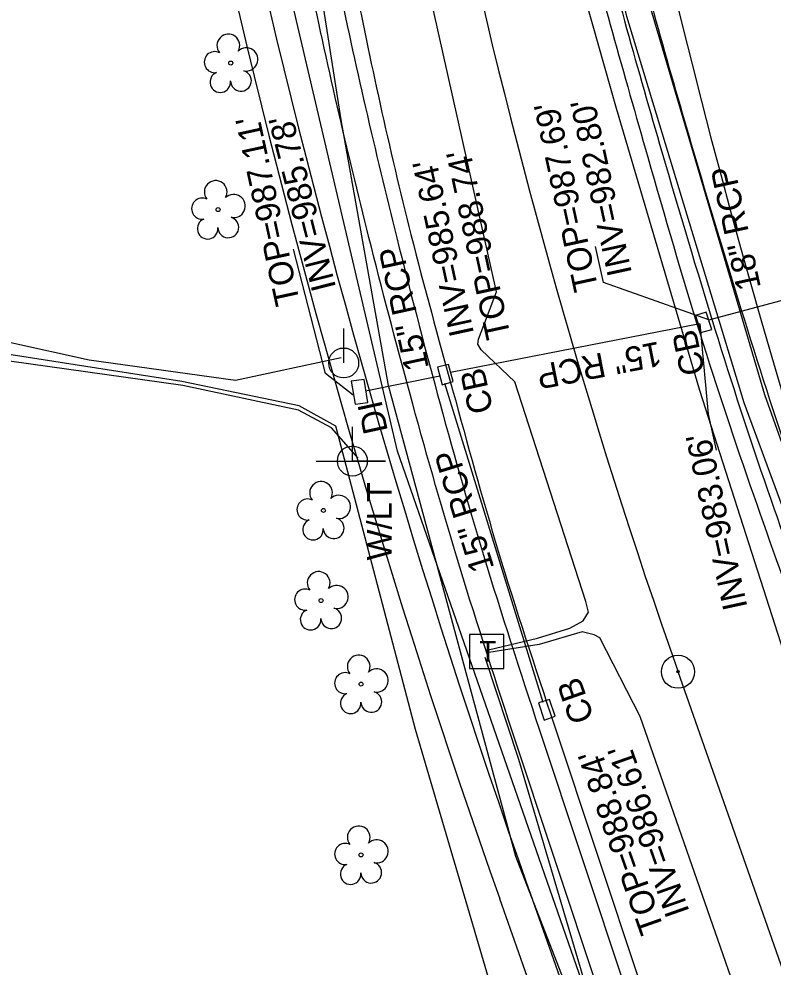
# Model space of a CAD drawing. Extents: x 1614611 to 1617571, y 898867 to 905462.
# Drawn here: x 1615972.1 to 1616095.5, y 904280.1 to 904435.2 of the extents above; entities that cross this region are included whole.
import ezdxf

# ---------------------------------------------------------------- set-up
doc = ezdxf.new("R2010")
doc.units = 0
for name, color, linetype in [('Exist Boundary Watershed Residential C 05', 7, 'Continuous'), ('Exist Horizontal Alignment Tick Label', 7, 'Continuous'), ('Exist Structure Minor Catch Basin Top Elevation', 7, 'Continuous'), ('Exist Structure Minor Drop Inlet Top Elevation', 7, 'Continuous'), ('Exist Structure Minor Pipes RCP 15 Inch Invert', 7, 'Continuous'), ('Exist Structure Minor Pipes RCP 18 Inch Invert', 7, 'Continuous'), ('Exist Survey Centerline Point CELL', 7, 'Continuous'), ('Exist Utilities Gas UG Line SUE LOS B', 7, 'Continuous'), ('Exist Utilities Power Joint Use Telephone CELL', 7, 'Continuous'), ('Exist Utilities Power Joint Use Telephone Text', 7, 'Continuous'), ('Exist Utilities Power Pole CELL', 7, 'Continuous'), ('Exist Utilities Telephone Pedestal CELL', 7, 'Continuous'), ('Exist Utilities Telephone UG Cable SUE LOS B', 7, 'Continuous'), ('Exist Utilities Telephone UG FO SUE LOS B', 7, 'Continuous'), ('Exist Utilities Telephone UG FO SUE LOS C', 7, 'Continuous'), ('Exist Utilities TV UG Cable SUE LOS B', 7, 'Continuous'), ('Exist Utilities TV UG FO Cable SUE LOS B', 7, 'Continuous'), ('Exist Utilities Water UG Line SUE LOS B', 7, 'Continuous'), ('Exist Vegetation Tree CELL', 7, 'Continuous'), ('Prop Drainage Structure Catch Basin Adjust CELL', 7, 'Continuous'), ('Prop Drainage Structure Catch Basin Grate 840 03E Label', 7, 'Continuous'), ('Prop Drainage Structure Catch Basin Open Throat 4 CELL', 7, 'Continuous'), ('Prop Drainage Structure Drop Inlet Grate 3 Narrow Slots and Sag Grates 840 24 Label', 7, 'Continuous'), ('Prop Drainage Structure Removal Label', 7, 'Continuous'), ('Prop Earthen Structure Cut Ditch Special Back of Curb Detail CELL', 7, 'Continuous'), ('Prop Earthen Structure Head Ditch Label', 7, 'Continuous'), ('Prop Easement Permanent Drainage', 7, 'Continuous'), ('Prop Erosion Embankment Toe Protection CELL', 7, 'Continuous'), ('Prop Erosion Embankment Toe Protection with Rip Rap 2 Detail CELL', 7, 'Continuous'), ('Prop Erosion Embankment Toe Protection with Rip Rap 3 Detail CELL', 7, 'Continuous'), ('Prop Plan Preparation Drainage Notes Label', 7, 'Continuous'), ('Prop Plan Preparation Table Ditch Data CELL', 7, 'Continuous'), ('Raster_Level_2', 7, 'Continuous'), ('Scratch_Level_1', 7, 'Continuous'), ('Scratch_Level_9', 7, 'Continuous')]:
    doc.layers.add(name, color=color, linetype=linetype)

# ---------------------------------------------------------------- blocks, each defined once
blk = doc.blocks.new('EXIST SURVEY CENTERLINE POINT')
at = {"layer": 'Exist Survey Centerline Point CELL'}
for radius in [0.0542, 0.00375]:
    blk.add_circle((0, 0), radius, dxfattribs=at)
blk = doc.blocks.new('EXIST UTILITIES TELEPHONE PEDESTAL')
at = {"layer": 'Exist Utilities Telephone Pedestal CELL'}
blk.add_line((0, 0), (0, 0), dxfattribs=at)
blk.add_lwpolyline([(-0.0545, -0.0565), (0.0574, -0.0565), (0.0574, 0.0554), (-0.0545, 0.0554), (-0.0545, -0.0565)], dxfattribs=at)
blk.add_text('T', height=0.0684, dxfattribs=at).set_placement((-0.0226, -0.0343))

msp = doc.modelspace()

# ---------------------------------------------------------------- linework, layer by layer
at = {"layer": 'Exist Boundary Watershed Residential C 05'}
msp.add_line((1616057.2, 904319.01), (1616071.33, 904276.54), dxfattribs=at)
for points in [[(1616036.89, 904712.38), (1616036.47, 904709.78), (1616036.41, 904704.57), (1616037.92, 904663.56), (1616040.29, 904622.52), (1616044.13, 904581.91), (1616049.52, 904539.43), (1616056.84, 904495.96), (1616066.12, 904453.97), (1616077.29, 904413.44), (1616085.97, 904384.46), (1616094.57, 904358.18), (1616103.14, 904334.3)], [(1615997.37, 904708.66), (1615998.49, 904661.09), (1616001.16, 904617.42), (1616004.97, 904575.65), (1616009.84, 904531.84), (1616016.05, 904486.99), (1616024.12, 904442.16), (1616033.92, 904399.38), (1616040.54, 904373.92), (1616048.1, 904347.47), (1616057.2, 904319.01)]]:
    msp.add_spline(points, degree=3, dxfattribs=at)
at = {"layer": 'Exist Utilities Gas UG Line SUE LOS B'}
msp.add_lwpolyline([(1616112.81, 904150.47), (1616095.02, 904196.89), (1616086.93, 904216.94), (1616080.62, 904232.37), (1616061.55, 904277.17), (1616053.37, 904298.2), (1616032.55, 904375.26), (1616024.82, 904418.68), (1616016.83, 904469.58), (1616008.07, 904526.35), (1616004.5, 904556.45)], dxfattribs=at)
at = {"layer": 'Exist Utilities Power Joint Use Telephone CELL'}
msp.add_line((1616026.64, 904362.88), (1616026.64, 904362.88), dxfattribs=at)
msp.add_lwpolyline([(1616020.71, 904362.88), (1616032.04, 904362.85), (1616026.64, 904362.86), (1616026.64, 904368.51)], dxfattribs=at)
msp.add_circle((1616026.64, 904362.89), 2.45, dxfattribs=at)
at = {"layer": 'Exist Utilities Power Pole CELL'}
for q in [(1616025.22, 904384.55), (1616025.22, 904378.93)]:
    msp.add_line((1616025.22, 904378.93), q, dxfattribs=at)
msp.add_circle((1616025.22, 904378.93), 2.45, dxfattribs=at)
at = {"layer": 'Exist Utilities Telephone UG Cable SUE LOS B'}
for points in [[(1616048.94, 904332.04), (1616056.91, 904333.91), (1616062.21, 904335.58), (1616064.42, 904336.78), (1616065.29, 904338.19), (1616064.86, 904339.94), (1616053.21, 904375.85), (1616047.74, 904381.07), (1616047.16, 904382.03), (1616047.3, 904382.84), (1616050.2, 904390.58), (1616036.77, 904450.77), (1616023.33, 904513.19), (1616016.15, 904558.39)], [(1616264.73, 903785.56), (1616225.23, 903895.34), (1616215.6, 903922.1), (1616202.44, 903959.77), (1616193.59, 903987.06), (1616171.78, 904048.65), (1616147.44, 904117.95), (1616126.43, 904148.49), (1616103.05, 904238.24), (1616092.8, 904266.31), (1616073.76, 904321.1), (1616067.14, 904333.96), (1616066.19, 904334.49), (1616064.27, 904334.96), (1616057.18, 904332.89), (1616048.96, 904331.57)], [(1616048.33, 904330.8), (1616053.85, 904314.12), (1616064.53, 904278.06), (1616076.61, 904243.93), (1616083.17, 904220.39), (1616080.21, 904212.01), (1616079.68, 904210.16), (1616080.3, 904208.81)]]:
    msp.add_lwpolyline(points, dxfattribs=at)
at = {"layer": 'Exist Utilities Telephone UG FO SUE LOS B'}
for points in [[(1616227.47, 903998.34), (1616211.12, 904046.11), (1616197.17, 904083.61), (1616180.84, 904129.23), (1616169.23, 904161.39), (1616162.49, 904178.57), (1616139.6, 904240.02), (1616090.77, 904372.44), (1616071.57, 904435.61), (1616056.71, 904499.76), (1616046.9, 904559.71)], [(1616172.98, 904168.79), (1616171.02, 904169.17), (1616169.94, 904170.68), (1616165.82, 904179.93), (1616142.94, 904241.46), (1616115.62, 904313.42), (1616094.14, 904373.71), (1616075.4, 904437.07), (1616059.87, 904500.59), (1616050.65, 904559.97)]]:
    msp.add_lwpolyline(points, dxfattribs=at)
at = {"layer": 'Exist Utilities Telephone UG FO SUE LOS C'}
msp.add_line((1616110.16, 904145.65), (1616034.02, 904364.51), dxfattribs=at)
msp.add_lwpolyline([(1616034.02, 904364.51), (1616014.41, 904448.18), (1615992.34, 904593.02)], dxfattribs=at)
at = {"layer": 'Exist Utilities TV UG Cable SUE LOS B'}
msp.add_lwpolyline([(1616027.58, 904363.35), (1616023.21, 904368.31), (1616017.83, 904371.19), (1615998.91, 904375.25), (1615970.55, 904379.25), (1615936.7, 904383.75), (1615897.49, 904393.93), (1615866.72, 904404.04), (1615862.97, 904406.89), (1615854.55, 904417.3), (1615840.06, 904422.53), (1615819.41, 904426.03), (1615794.82, 904424.38), (1615770.62, 904419.24), (1615748.65, 904413.39), (1615748.63, 904413.39)], dxfattribs=at)
at = {"layer": 'Exist Utilities TV UG FO Cable SUE LOS B'}
msp.add_lwpolyline([(1616082.03, 904205.63), (1616078.76, 904211.5), (1616072.95, 904217.64), (1616063.83, 904236.79), (1616050.03, 904274.65), (1616036.99, 904318.99), (1616023.92, 904368.58), (1616017.91, 904371.93), (1615998.76, 904375.92), (1615970.79, 904380.24), (1615936.88, 904384.46), (1615897.53, 904394.73), (1615867.22, 904404.56), (1615863.54, 904407.73), (1615855.35, 904417.46), (1615839.69, 904423.44), (1615819.45, 904426.72), (1615794.88, 904425.22), (1615770.33, 904420), (1615748.51, 904414.05)], dxfattribs=at)
at = {"layer": 'Exist Utilities Water UG Line SUE LOS B'}
msp.add_lwpolyline([(1616526.94, 903118.95), (1616504.59, 903181.23), (1616480.02, 903252.46), (1616446.17, 903345), (1616411.28, 903445.17), (1616385.62, 903515.15), (1616350.02, 903616.87), (1616323.73, 903691.37), (1616291.21, 903786.26), (1616260.45, 903872.07), (1616224.66, 903974.02), (1616192.08, 904066.13), (1616173.94, 904118.11), (1616130.42, 904237.78), (1616097.26, 904331.65), (1616083.48, 904374.45), (1616069.85, 904420.53), (1616059.14, 904458.49), (1616050.85, 904496.39), (1616045.84, 904527.76), (1616030.28, 904669.9)], dxfattribs=at)
at = {"layer": 'Exist Vegetation Tree CELL'}
for p, q in [((1616006.73, 904427.99), (1616006.73, 904427.99)), ((1616004.67, 904404.02), (1616004.67, 904404.02)), ((1616021.91, 904354.81), (1616021.91, 904354.81)), ((1616021.51, 904340.08), (1616021.51, 904340.08)), ((1616028.07, 904326.4), (1616028.07, 904326.4)), ((1616028.06, 904298.47), (1616028.06, 904298.47))]:
    msp.add_line(p, q, dxfattribs=at)
for centre in [(1616006.73, 904427.99), (1616004.67, 904404.02), (1616021.91, 904354.81), (1616021.51, 904340.08), (1616028.07, 904326.4), (1616028.06, 904298.47)]:
    msp.add_circle(centre, 0.326, dxfattribs=at)
for centre, radius, start, end in [((1616006.35, 904430.86), 1.86, 330.1651, 219.7134), ((1616009.28, 904428.58), 1.9, 257.1011, 134.1999), ((1616004.13, 904428.14), 1.73, 62.6636, 279.3457), ((1616005.03, 904424.87), 1.69, 111.5671, 6.231), ((1616008.41, 904425.09), 1.7, 181.2822, 74.56), ((1616004.28, 904406.9), 1.86, 330.1651, 219.7134), ((1616002.06, 904404.18), 1.73, 62.6636, 279.3457), ((1616007.22, 904404.61), 1.9, 257.1011, 134.1999), ((1616002.96, 904400.9), 1.69, 111.5671, 6.231), ((1616006.34, 904401.12), 1.7, 181.2822, 74.56), ((1616021.52, 904357.68), 1.86, 330.1651, 219.7134), ((1616019.3, 904354.96), 1.73, 62.6636, 279.3457), ((1616024.46, 904355.39), 1.9, 257.1011, 134.1999), ((1616020.2, 904351.68), 1.69, 111.5671, 6.231), ((1616023.58, 904351.91), 1.7, 181.2822, 74.56), ((1616021.13, 904342.95), 1.86, 330.1651, 219.7134), ((1616018.91, 904340.23), 1.73, 62.6636, 279.3457), ((1616024.06, 904340.66), 1.9, 257.1011, 134.1999), ((1616023.19, 904337.18), 1.7, 181.2822, 74.56), ((1616019.81, 904336.95), 1.69, 111.5671, 6.231), ((1616027.68, 904329.28), 1.86, 330.1651, 219.7134), ((1616025.46, 904326.56), 1.73, 62.6636, 279.3457), ((1616030.62, 904326.99), 1.9, 257.1011, 134.1999), ((1616026.36, 904323.28), 1.69, 111.5671, 6.231), ((1616029.74, 904323.5), 1.7, 181.2822, 74.56), ((1616027.68, 904301.34), 1.86, 330.1651, 219.7134), ((1616025.46, 904298.62), 1.73, 62.6636, 279.3457), ((1616030.61, 904299.05), 1.9, 257.1011, 134.1999), ((1616026.36, 904295.34), 1.69, 111.5671, 6.231), ((1616029.73, 904295.57), 1.7, 181.2822, 74.56)]:
    msp.add_arc(centre, radius, start, end, dxfattribs=at)
at = {"layer": 'Prop Drainage Structure Catch Basin Grate 840 03E Label'}
msp.add_lwpolyline([(1616024.8, 904379.75), (1616007.51, 904376.09), (1615983.58, 904379.37), (1615970.76, 904382.21), (1615936.94, 904387.13), (1615897.7, 904396.33), (1615868.35, 904406.71), (1615862.89, 904413.51), (1615851.92, 904436.53), (1615843.3, 904450.47), (1615836.53, 904457.93), (1615811.09, 904476.14), (1615780.1, 904485.64), (1615765.05, 904484.84), (1615750.44, 904471.86), (1615740.03, 904463.22)], dxfattribs=at)
at = {"layer": 'Prop Drainage Structure Catch Basin Open Throat 4 CELL'}
for points in [[(1616084.55, 904387.26), (1616082.76, 904386.71), (1616083.67, 904383.89), (1616085.44, 904384.43), (1616084.55, 904387.26)], [(1616041.33, 904375.36), (1616043.13, 904375.88), (1616042.38, 904378.7), (1616040.58, 904378.23), (1616041.33, 904375.36)], [(1616058.01, 904320.52), (1616059.81, 904321.14), (1616058.9, 904323.9), (1616057.09, 904323.36), (1616058.01, 904320.52)]]:
    msp.add_lwpolyline(points, dxfattribs=at)
at = {"layer": 'Prop Drainage Structure Removal Label'}
msp.add_lwpolyline([(1616083.48, 904385.36), (1616084.88, 904370.55), (1616086.16, 904364.68)], dxfattribs=at)
at = {"layer": 'Prop Earthen Structure Cut Ditch Special Back of Curb Detail CELL'}
msp.add_line((1616104.42, 904139.48), (1616050.75, 904291.28), dxfattribs=at)
msp.add_arc((1617381.7, 904761.87), 1411.7, 186.43736, 199.47247, dxfattribs=at)
at = {"layer": 'Prop Earthen Structure Head Ditch Label'}
msp.add_line((1616055.46, 904292.95), (1616109.14, 904141.14), dxfattribs=at)
for centre, radius, start, end in [((1617328.59, 904741.62), 1285.26, 180.58714, 198.28426), ((1617381.7, 904761.87), 1406.7, 186.43736, 199.47247)]:
    msp.add_arc(centre, radius, start, end, dxfattribs=at)
at = {"layer": 'Prop Erosion Embankment Toe Protection CELL'}
msp.add_lwpolyline([(1616027.09, 904372.19), (1616029.16, 904372.48), (1616028.56, 904376.25), (1616026.46, 904375.93), (1616027.09, 904372.19)], dxfattribs=at)
at = {"layer": 'Prop Erosion Embankment Toe Protection with Rip Rap 3 Detail CELL'}
msp.add_line((1616084.97, 904385.98), (1616105.4, 904391.46), dxfattribs=at)
at = {"layer": 'Prop Plan Preparation Drainage Notes Label'}
for points in [[(1616084.97, 904385.98), (1616067.71, 904392.12), (1616066.43, 904397.99)], [(1616026.77, 904373.64), (1616022.25, 904377.23), (1616022.25, 904377.23), (1616017, 904397.57)]]:
    msp.add_lwpolyline(points, dxfattribs=at)
at = {"layer": 'Prop Plan Preparation Table Ditch Data CELL'}
for p, q in [((1616083.48, 904385.36), (1616042.7, 904377.35)), ((1616040.93, 904376.8), (1616028.81, 904374.3)), ((1616041.71, 904375.62), (1616057.82, 904323.47))]:
    msp.add_line(p, q, dxfattribs=at)
at = {"layer": 'Raster_Level_2'}
msp.add_line((1616145.53, 904142.15), (1616079.93, 904328.43), dxfattribs=at)
msp.add_arc((1617077.64, 904679.78), 1057.77, 185.13333, 199.4, dxfattribs=at)
at = {"layer": 'Scratch_Level_1'}
msp.add_line((1616066.88, 904276.41), (1616052.78, 904318.7), dxfattribs=at)
for points in [[(1616041.38, 904704.69), (1616042.91, 904663.74), (1616045.28, 904623.06), (1616049.16, 904582.4), (1616054.54, 904539.86), (1616061.85, 904496.88), (1616070.96, 904455.18), (1616082.1, 904414.74), (1616090.78, 904386), (1616099.26, 904359.95), (1616107.9, 904336.06)], [(1616052.78, 904318.7), (1616043.67, 904347.34), (1616036.08, 904373.84), (1616029.35, 904399.46), (1616019.45, 904442.61), (1616011.39, 904487.69), (1616005.24, 904532.38), (1616000.37, 904576.64), (1615999.71, 904583.21)]]:
    msp.add_spline(points, degree=3, dxfattribs=at)
at = {"layer": 'Scratch_Level_9'}
msp.add_line((1616059.66, 904319.75), (1616073.76, 904277.43), dxfattribs=at)
for points in [[(1616075.74, 904745.69), (1616063.59, 904746.06), (1616055.4, 904744.64), (1616049.66, 904742.08), (1616047.05, 904740.31), (1616042.03, 904735.52), (1616039.5, 904732.38), (1616037.34, 904728.4), (1616035.1, 904719.25), (1616034.05, 904709.96), (1616033.94, 904704.26), (1616035.54, 904663.34), (1616037.88, 904622.38), (1616041.67, 904581.5), (1616047.12, 904539.04), (1616054.36, 904495.38), (1616063.72, 904453.46), (1616074.98, 904412.62), (1616083.53, 904383.7), (1616092.27, 904357.36), (1616100.84, 904333.27)], [(1615999.9, 904708.5), (1616000.91, 904661.48), (1616003.66, 904617.61), (1616007.31, 904575.9), (1616012.19, 904532.13), (1616018.48, 904487.41), (1616026.69, 904442.67), (1616036.22, 904399.95), (1616043.04, 904374.54), (1616050.52, 904348.16), (1616059.66, 904319.75)]]:
    msp.add_spline(points, degree=3, dxfattribs=at)

# ---------------------------------------------------------------- block references
at = {"layer": 'Exist Horizontal Alignment Tick Label', "xscale": 50, "yscale": 50, "rotation": 1.7967031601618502e-12}
msp.add_blockref('EXIST SURVEY CENTERLINE POINT', (1616079.93, 904328.43), dxfattribs=at)
at = {"layer": 'Exist Utilities Telephone Pedestal CELL', "xscale": 50, "yscale": 50}
msp.add_blockref('EXIST UTILITIES TELEPHONE PEDESTAL', (1616048.55, 904331.77), dxfattribs=at)

# ---------------------------------------------------------------- texts
at = {"layer": 'Exist Structure Minor Catch Basin Top Elevation'}
for s, rotation, p in [("TOP=987.69'", 102.2667, (1616066.9, 904391.11)), ("TOP=988.74'", 102.2667, (1616052.55, 904383.31)), ("TOP=988.84'", 109.4, (1616077.7, 904286.34))]:
    msp.add_text(s, height=4, rotation=rotation, dxfattribs=at).set_placement(p)
at = {"layer": 'Exist Structure Minor Drop Inlet Top Elevation'}
msp.add_text("TOP=987.11'", height=4, rotation=102.2667, dxfattribs=at).set_placement((1616018.07, 904388.81))
at = {"layer": 'Exist Structure Minor Pipes RCP 15 Inch Invert'}
for s, rotation, p in [("INV=985.78'", 104.2649, (1616024, 904391.26)), ("INV=985.64'", 102.2667, (1616046.57, 904383.75)), ("INV=983.06'", 102.2667, (1616091.31, 904338.99)), ("INV=986.61'", 109.4, (1616081.85, 904289.18))]:
    msp.add_text(s, height=4, rotation=rotation, dxfattribs=at).set_placement(p)
at = {"layer": 'Exist Structure Minor Pipes RCP 18 Inch Invert'}
msp.add_text("INV=982.80'", height=4, rotation=102.2667, dxfattribs=at).set_placement((1616072.41, 904393.64))
at = {"layer": 'Exist Utilities Power Joint Use Telephone Text'}
msp.add_text('W/LT', height=4, rotation=90, dxfattribs=at).set_placement((1616033.06, 904346.65))
at = {"layer": 'Prop Drainage Structure Catch Basin Adjust CELL'}
msp.add_text('DI', height=4, rotation=102.2667, dxfattribs=at).set_placement((1616032.48, 904367.81))
at = {"layer": 'Prop Drainage Structure Drop Inlet Grate 3 Narrow Slots and Sag Grates 840 24 Label'}
msp.add_text('18" RCP', height=4, rotation=102.2667, dxfattribs=at).set_placement((1616093.51, 904391.29))
at = {"layer": 'Prop Easement Permanent Drainage'}
for rotation, p in [(102.2667, (1616084.37, 904377.38)), (102.2667, (1616049.7, 904371.11)), (109.4, (1616066.25, 904320.81))]:
    msp.add_text('CB', height=4, rotation=rotation, dxfattribs=at).set_placement(p)
at = {"layer": 'Prop Erosion Embankment Toe Protection with Rip Rap 2 Detail CELL'}
for rotation, p in [(102.2667, (1616039.19, 904378.13)), (191.1223, (1616076.76, 904382.48)), (107.1684, (1616049.9, 904345.41))]:
    msp.add_text('15" RCP', height=4, rotation=rotation, dxfattribs=at).set_placement(p)

doc.saveas('drawing.dxf')
